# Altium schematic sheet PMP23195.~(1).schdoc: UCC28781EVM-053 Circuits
size 431 x 279 mm; Date: Not shown in title block; ApprovedBy: Not shown in title block; CheckedBy: Not shown in title block; Author: Not shown in title block; CompanyName: Not shown in title block; DrawnBy: U. Goerke; Engineer: Not shown in title block; Organization: Not shown in title block; Address1: Not shown in title block; Address2: Not shown in title block; Address3: Not shown in title block; Address4: Not shown in title block; DocumentNumber: 1; Revision: Use project parameter SCH_Rev; SheetNumber: 1; SheetTotal: 2; PageSetup: Record=PageOptions¦CenterHorizontal=True¦CenterVertical=True¦PrintScale=1.00¦XCorrection=1.00¦YCorrection=1.00¦PrintKind=0¦BorderSize=5000000¦LeftOffset=0¦BottomOffset=0¦Orientation=2¦PaperLength=1000¦PaperWidth=1000¦Scale=100¦PaperSource=15¦PrintQuality=600¦MediaType=1¦DitherType=10¦PaperKind=Letter¦PrintScaleMode=1
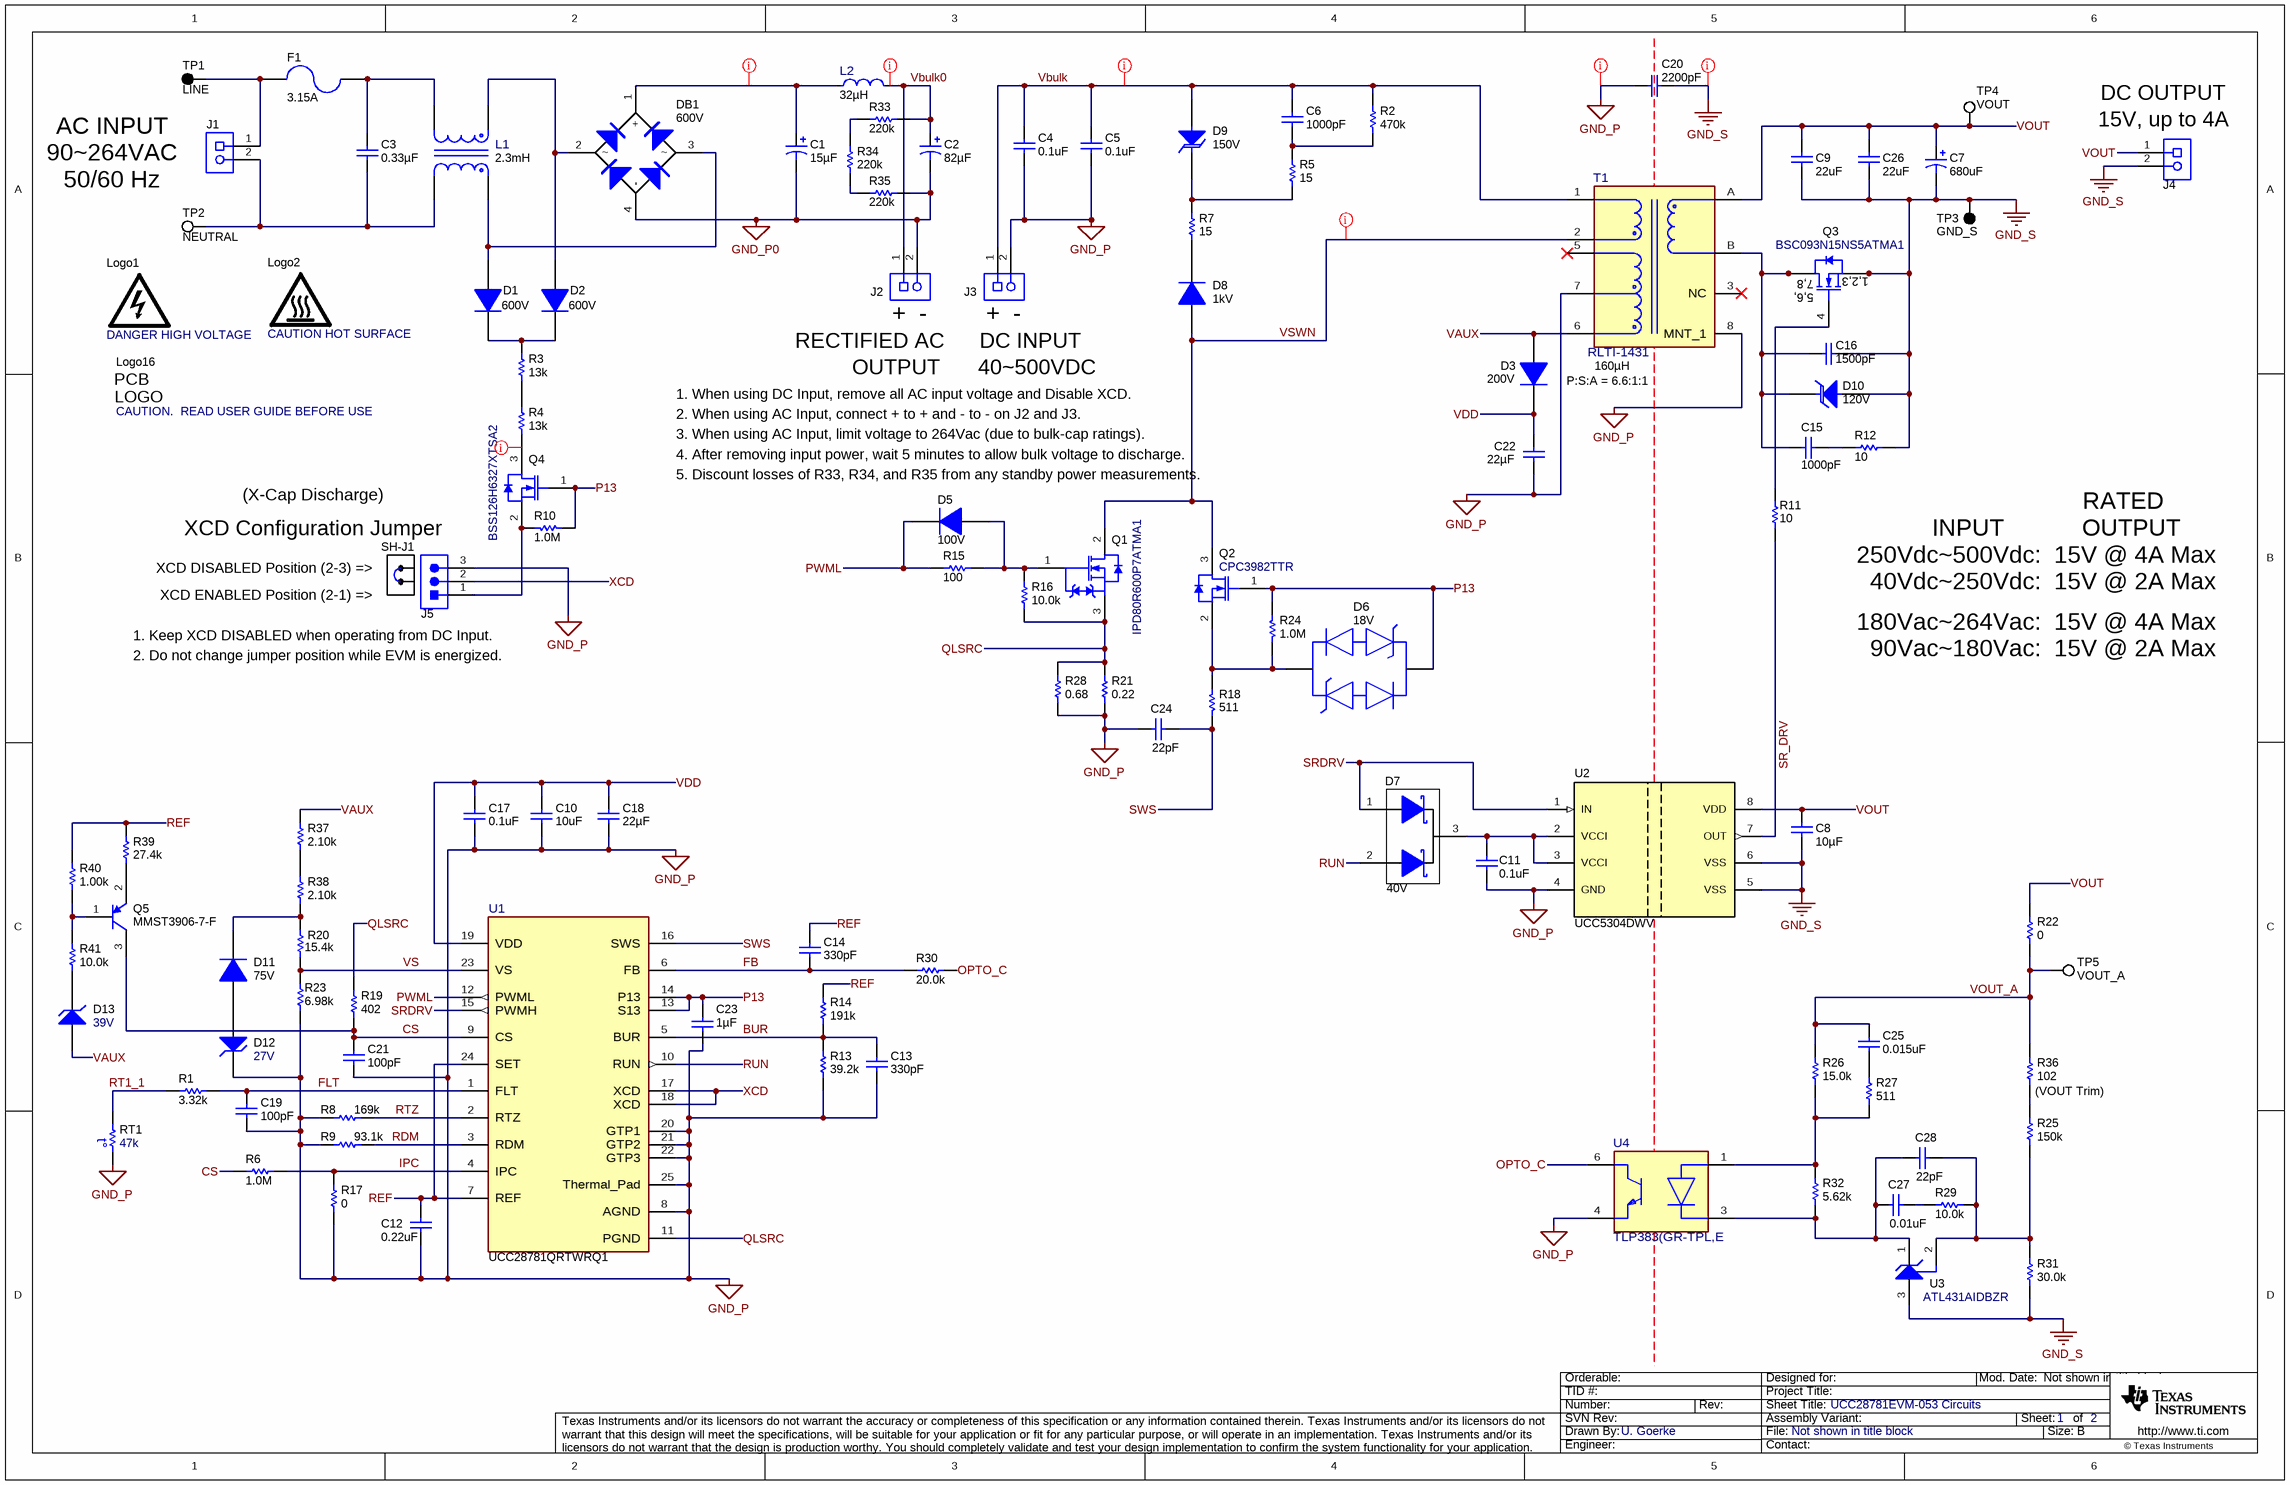
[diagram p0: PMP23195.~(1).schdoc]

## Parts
C1  ValueDisplayed: 15µF  [UVC_1000x1600]  (hidden comment: UVC2G150MPD)
C2  ValueDisplayed: 82µF  [Rubycon_1800x2500_HD]  (hidden comment: 400BXW82MEFR18X25)
C3  ValueDisplayed: 0.33µF  [WCAP-FTX2_1500x850]  (hidden comment: 890324024003)
C4  ValueDisplayed: 0.1uF  [1210_280]  (hidden comment: C1210C104KBRAC7800)
C5  ValueDisplayed: 0.1uF  [1210_280]  (hidden comment: C1210C104KBRAC7800)
C6  ValueDisplayed: 1000pF  [1206L]  (hidden comment: GRM31BR72J102KW01L)
C7  ValueDisplayed: 680uF  [PSG_1000x1150]  (hidden comment: APSG200ELL681MJB5S)
C8  ValueDisplayed: 10µF  [1206_180L]  (hidden comment: C1206C106J3RACAUTO)
C9  ValueDisplayed: 22uF  [1210_270L]  (hidden comment: GRM32ER71E226KE15L)
C10  ValueDisplayed: 10uF  [1206_180L]  (hidden comment: C3216X5R1H106K160AB)
C11  ValueDisplayed: 0.1uF  [0402S]  (hidden comment: GRM155R71H104ME14D)
C12  ValueDisplayed: 0.22uF  [0402S]  (hidden comment: GRM155R71C224KA12D)
C13  ValueDisplayed: 330pF  [0402S]  (hidden comment: GRM155R71H331KA01D)
C14  ValueDisplayed: 330pF  [0402S]  (hidden comment: GRM155R71H331KA01D)
C15  ValueDisplayed: 1000pF  [0805L]  (hidden comment: GRM21AR72E102KW01D)
C16  ValueDisplayed: 1500pF  [0805_HV1]  (hidden comment: GRM21AR72E152KW01D)
C17  ValueDisplayed: 0.1uF  [0402S]  (hidden comment: GRM155R71H104ME14D)
C18  ValueDisplayed: 22µF  [1210L]  (hidden comment: GMK325BJ226MM-P)
C19  ValueDisplayed: 100pF  [0402S]  (hidden comment: GRM1555C1H101JA01D)
C20  ValueDisplayed: 2200pF  [C900_9x13]  (hidden comment: C921U222MVVDBA7317)
C21  ValueDisplayed: 100pF  [0402S]  (hidden comment: GRM1555C1H101JA01D)
C22  ValueDisplayed: 22µF  [1210L]  (hidden comment: GMK325BJ226MM-P)
C23  Cap_F: 1µF  [0603S]  (hidden comment: CGA3E1X7R1V105K080AC)
C24  ValueDisplayed: 22pF  [0402S]  (hidden comment: GCM1555C1H220JA16D)
C25  ValueDisplayed: 0.015uF  [0402S]  (hidden comment: GRM155R71H153KA12D)
C26  ValueDisplayed: 22uF  [1210_270L]  (hidden comment: GRM32ER71E226KE15L)
C27  ValueDisplayed: 0.01uF  [0402S]  (hidden comment: GRM155R71H103KA88D)
C28  ValueDisplayed: 22pF  [0402S]  (hidden comment: GCM1555C1H220JA16D)
D1  Vr_V: 600V  [TUMD2SM]  (hidden comment: RFU02VSM6STR)
D2  Vr_V: 600V  [TUMD2SM]  (hidden comment: RFU02VSM6STR)
D3  Vr_V: 200V  [SOD-123H]  (hidden comment: CSFMT104-HF)
D5  Vr_V: 100V  [SOD-323]  (hidden comment: BAS316,115)
D6  value 18V  [FP-CDSOD323-T18C_SOD323-MFG]  (hidden comment: CDSOD323-T18C)
D7  Vr_V: 40V  [SOT-323]  (hidden comment: BAS40W-05-7-F)
D8  Vr_V: 1kV  [SMA]  (hidden comment: MRA4007T3G)
D9  VRWM: 150V  [SMA]  (hidden comment: SMAJ150A)
D10  VRWM: 120V  [SMA]  (hidden comment: SMAJ120A)
D11  Vr_V: 75V  [SOD-523]  (hidden comment: 1N4148X-TP)
D12  value 27V  [SOD-323]  (hidden comment: SZMM3Z27VST1G)
D13  value 39V  [SOD-523]  (hidden comment: BZT585B39T-7)
DB1  value 600V  [Z4-D]  (hidden comment: Z4DGP406L-HF)
F1  Irating_A: 3.15A  [FUSE_392]  (hidden comment: 39213150000)
J1  ED120/2DS  [On-Shore_ED120_2DS]  (value not drawn)
J2  ED120/2DS  [On-Shore_ED120_2DS]  (value not drawn)
J3  ED120/2DS  [On-Shore_ED120_2DS]  (value not drawn)
J4  ED120/2DS  [On-Shore_ED120_2DS]  (value not drawn)
J5  TSW-103-07-G-S  [TSW-103-07-G-S]  (value not drawn)
L1  Ind_H: 2.3mH  [FP-RLTI-1387_PTH_CMC_0IN38_0IN60-MFG]  (hidden comment: RLTI-1387)
L2  Ind_H: 32µH  [FP-7447052_PTH_D10MM0-MFG]  (hidden comment: 7447052)
Logo1  DANGER HIGH VOLTAGE  [IEC_HighVoltage_Small]  (no BOM)
Logo2  CAUTION HOT SURFACE  [IEC_HotSurface_Small]  (no BOM)
Logo16  CAUTION.  READ USER GUIDE BEFORE USE  [IEC_Caution_Small]  (no BOM)
Q1  IPD80R600P7ATMA1  [DPAK]
Q2  CPC3982TTR  [SOT-23L]
Q3  BSC093N15NS5ATMA1  [PG-TDSON-8]
Q4  BSS126H6327XTSA2  [SOT-23L]
Q5  MMST3906-7-F  [SOT-323]
R1  ValueDisplayed: 3.32k  [0402S]  (hidden comment: CRCW04023K32FKED)
R2  ValueDisplayed: 470k  [0805_HV1]  (hidden comment: CRCW0805470KJNEA)
R3  ValueDisplayed: 13k  [1206L]  (hidden comment: CRCW120613K0JNEA)
R4  ValueDisplayed: 13k  [1206L]  (hidden comment: CRCW120613K0JNEA)
R5  ValueDisplayed: 15  [0805_HV1]  (hidden comment: CRCW080515R0JNEA)
R6  ValueDisplayed: 1.0M  [0402S]  (hidden comment: CRCW04021M00JNED)
R7  ValueDisplayed: 15  [0805_HV1]  (hidden comment: CRCW080515R0JNEA)
R8  ValueDisplayed: 169k  [0402S]  (hidden comment: CRCW0402169KFKED)
R9  ValueDisplayed: 93.1k  [0402S]  (hidden comment: CRCW040293K1FKED)
R10  ValueDisplayed: 1.0M  [0402S]  (hidden comment: CRCW04021M00JNED)
R11  ValueDisplayed: 10  [0402S]  (hidden comment: CRCW040210R0JNED)
R12  ValueDisplayed: 10  [1206L]  (hidden comment: CRCW120610R0JNEA)
R13  ValueDisplayed: 39.2k  [0402S]  (hidden comment: CRCW040239K2FKED)
R14  ValueDisplayed: 191k  [0402S]  (hidden comment: CRCW0402191KFKED)
R15  ValueDisplayed: 100  [0805_HV1]  (hidden comment: CRCW0805100RJNEA)
R16  ValueDisplayed: 10.0k  [0402S]  (hidden comment: CRCW040210K0FKED)
R17  ValueDisplayed: 0  [0402S]  (hidden comment: CRCW04020000Z0EDHP)
R18  ValueDisplayed: 511  [0402S]  (hidden comment: CRCW0402511RFKED)
R19  ValueDisplayed: 402  [0402S]  (hidden comment: CRCW0402402RFKED)
R20  ValueDisplayed: 15.4k  [0402S]  (hidden comment: CRCW040215K4FKED)
R21  ValueDisplayed: 0.22  [1210L]  (hidden comment: MCR25JZHFLR220)
R22  ValueDisplayed: 0  [0402S]  (hidden comment: RC0402JR-070RL)
R23  ValueDisplayed: 6.98k  [0402S]  (hidden comment: CRCW04026K98FKED)
R24  ValueDisplayed: 1.0M  [0402S]  (hidden comment: CRCW04021M00JNED)
R25  ValueDisplayed: 150k  [0402S]  (hidden comment: ERJ-2RKF1503X)
R26  ValueDisplayed: 15.0k  [0402S]  (hidden comment: CRCW040215K0FKED)
R27  ValueDisplayed: 511  [0402S]  (hidden comment: CRCW0402511RFKED)
R28  ValueDisplayed: 0.68  [0805_HV1]  (hidden comment: ERJ-6RQFR68V)
R29  ValueDisplayed: 10.0k  [0402S]  (hidden comment: CRCW040210K0FKED)
R30  ValueDisplayed: 20.0k  [0402S]  (hidden comment: CRCW040220K0FKED)
R31  ValueDisplayed: 30.0k  [0402S]  (hidden comment: CRCW040230K0FKED)
R32  ValueDisplayed: 5.62k  [0402S]  (hidden comment: CRCW04025K62FKED)
R33  ValueDisplayed: 220k  [1206]  (hidden comment: CRCW1206220KJNEA)
R34  ValueDisplayed: 220k  [1206]  (hidden comment: CRCW1206220KJNEA)
R35  ValueDisplayed: 220k  [1206]  (hidden comment: CRCW1206220KJNEA)
R36  ValueDisplayed: 102  [0402S]  (hidden comment: CRCW0402102RFKED)
R37  ValueDisplayed: 2.10k  [0402S]  (hidden comment: CRCW04022K10FKED)
R38  ValueDisplayed: 2.10k  [0402S]  (hidden comment: CRCW04022K10FKED)
R39  ValueDisplayed: 27.4k  [0402S]  (hidden comment: CRCW040227K4FKED)
R40  ValueDisplayed: 1.00k  [0402S]  (hidden comment: CRCW04021K00FKED)
R41  ValueDisplayed: 10.0k  [0402S]  (hidden comment: CRCW040210K0FKED)
RT1  value 47k  [0603S]  (hidden comment: NCP18WB473J03RB)
SH-J1  SNT-100-BK-T-H  [SNT-100-BK-x-H]  (value not drawn)
T1  RLTI-1431  Ind_H: 160µH  [FP-RLTI-1431_PTH8_1IN0_0IN91-MFG]
TP1  LINE  [Keystone5011]
TP2  NEUTRAL  [Keystone5012]
TP3  GND_S  [Keystone5011]
TP4  VOUT  [Keystone5012]
TP5  VOUT_A  [Keystone5012]
U1  UCC28781QRTWRQ1  [RTW0024B-MFG]
U2  UCC5304DWV  [DWV0008A]
U3  ATL431AIDBZR  [DBZ0003A_L]
U4  TLP383(GR-TPL,E  [FP-TLP383(GR-TPL,E_SO6-4-MFG]

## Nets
GND_P: C4.1 C5.1 C10.2 C11.2 C12.2 C13.2 C17.2 C18.1 C19.1 C20.2 C21.2 C22.1 C23.2 C24.1 D12.1(K) J3.2 J5.3 R8.1 R9.1 R13.2 R17.1 R21.1 R23.1 R28.2 RT1.2 T1.7 T1.8(MNT_1) U1.8(AGND) U1.20(GTP1) U1.21(GTP2) U1.22(GTP3) U1.25(Thermal_Pad) U2.4(GND) U4.4(Emitter)
GND_P0: C1.2(-) C2.2(-) DB1.4(-) J2.2 R35.1
GND_S: C7.2(-) C8.2 C9.2 C16.2 C20.1 C26.2 D10.2(A) J4.2 Q3.1(S) Q3.2(S) Q3.3(S) R12.1 R31.2 TP3.1 U2.5(VSS) U2.6(VSS) U3.3(ANODE)
BUR: C13.1 R13.1 R14.2 U1.5(BUR)
CS: C21.1 Q5.3(C) R6.2 R19.1 U1.9(CS)
FB: C14.2 R30.1 U1.6(FB)
FLT: C19.2 R1.2 U1.1(FLT)
IPC: R6.1 R17.2 U1.4(IPC)
OPTO_C: R30.2 U4.6(Collector)
P13: C23.1 D6.2 Q2.1(G) Q4.1(G) R10.2 R24.2 U1.13(S13) U1.14(P13)
PWML: D5.1(K) R15.1 U1.12(PWML)
QLSRC: Q1.3(S) R16.1 R19.2 R21.2 R28.1 U1.11(PGND)
RDM: R9.2 U1.3(RDM)
REF: C12.1 C14.1 R14.1 R39.1 R40.1 U1.7(REF) U1.24(SET)
RT1_1: R1.1 RT1.1
RTZ: R8.2 U1.2(RTZ)
RUN: D7.2(A) U1.10(RUN)
SR_DRV: R11.1 U2.7(OUT)
SRDRV: D7.1(A) U1.15(PWMH) U2.1(IN)
SWS: C24.2 R18.1 U1.16(SWS)
VAUX: D3.2(A) D13.2(A) R37.1 T1.6
Vbulk: C4.2 C5.2 C6.1 D9.2(A) J3.1 R2.2 T1.1
Vbulk0: C2.1(+) J2.1 L2.2 R33.2
VDD: C10.1 C17.1 C18.2 C22.2 D3.1(K) U1.19(VDD)
VOUT: C7.1(+) C8.1 C9.1 C26.1 J4.1 R22.1 T1.A TP4.1 U2.8(VDD)
VOUT_A: C25.2 R22.2 R26.2 R36.1 TP5.1
VS: R20.2 R23.2 U1.23(VS)
VSWN: D8.2(A) Q1.2(D) Q2.3(D) T1.2
XCD: J5.2 U1.17(XCD) U1.18(XCD)
NetC1_1: C1.1(+) DB1.1(+) L2.1
NetC3_1: C3.1 J1.2 L1.2 TP2.1
NetC3_2: C3.2 F1.1 L1.3
NetC6_2: C6.2 R2.1 R5.2
NetC11_1: C11.1 D7.3(K) U2.2(VCCI) U2.3(VCCI)
NetC15_1: C15.1 R12.2
NetC15_2: C15.2 C16.1 D10.1(K) Q3.5(D) Q3.6(D) Q3.7(D) Q3.8(D) Q3.9(D) T1.B
NetC25_1: C25.1 R27.2
NetC27_1: C27.1 R29.1
NetC27_2: C27.2 C28.1 R32.1 U3.1(CATHODE) U4.3(Cathode)
NetC28_2: C28.2 R25.1 R29.2 R31.1 U3.2(REF)
NetD1_1: D1.1(K) D2.1(K) R3.1
NetD1_2: D1.2(A) DB1.3 L1.1
NetD2_2: D2.2(A) DB1.2 L1.4
NetD5_2: D5.2(A) Q1.1(G) R15.2 R16.2
NetD6_1: D6.1 Q2.2(S) R18.2 R24.1
NetD8_1: D8.1(K) R7.1
NetD9_1: D9.1(K) R5.1 R7.2
NetD11_1: D11.1(K) R20.1 R38.2
NetD11_2: D11.2(A) D12.2(A)
NetD13_1: D13.1(K) R41.2
NetF1_2: F1.2 J1.1 TP1.1
NetJ5_1: J5.1 Q4.2(S) R10.1
NetQ3_4: Q3.4(G) R11.2
NetQ4_3: Q4.3(D) R4.2
NetQ5_1: Q5.1(B) R40.2 R41.1
NetQ5_2: Q5.2(E) R39.2
NetR3_2: R3.2 R4.1
NetR25_2: R25.2 R36.2
NetR26_1: R26.1 R27.1 R32.2 U4.1(Anode)
NetR33_1: R33.1 R34.2
NetR34_1: R34.1 R35.2
NetR37_2: R37.2 R38.1

Not connected (* = marked no-connect by the designer): T1 3(NC)* 5*

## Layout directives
net class HV: NetC1_1, NetQ4_3, Vbulk, Vbulk0, VSWN
net class Primary: GND_P
net class Secondary: GND_S

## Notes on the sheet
- (near J4) DC OUTPUT
- 90|64VAC
- AC INPUT
- (near J4) 15V, up to 4A
- 50/60 Hz
- RECTIFIED AC
- OUTPUT
- (near J2) +  -
- (near J3) +  -
- DC INPUT
- 40~500VDC
- 1. When using DC Input, remove all AC input voltage and Disable XCD.
- 2. When using AC Input, connect + to + and - to - on J2 and J3.
- 3. When using AC Input, limit voltage to 264Vac (due to bulk-cap ratings).
- P:S:A = 6.6:1:1
- (X-Cap Discharge)
- 4. After removing input power, wait 5 minutes to allow bulk voltage to discharge.
- (near D5) 5. Discount losses of R33, R34, and R35 from any standby power measurements.
- RATED
- XCD Configuration Jumper
- (near SH-J1) XCD DISABLED Position (2-3) =>
- 250Vdc~500Vdc:  15V @ 4A Max
- INPUT            OUTPUT
- 1. Keep XCD DISABLED when operating from DC Input.
- (near SH-J1) XCD ENABLED Position (2-1) =>
- 180Vac|64Vac:  15V @ 4A Max
- 40Vdc|50Vdc:  15V @ 2A Max
- 2. Do not change jumper position while EVM is energized.
- 90Vac
  80Vac:  15V @ 2A Max
- (near R36) (VOUT Trim)

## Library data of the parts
C1 = CMP-0860955-2: CAP, AL, 15 µF, 400 V, +/- 20%, AEC-Q200 Grade 2, TH; Manufacturer: Nichicon; SizeArea_mm2: 100; CompType: Capacitor; Value2: 400V; SizeZ_mm: 18; IRMS_A: 180mA; Polarized: Y; SizeX_mm: 10; Value: 15uF; TaMin_C: -40°C; AEC Grade: 2; U/M: EA; SizeAreaWB_mm2: 144; Cap_Case: 10x16; TaMax_C: 105°C; AEC Category: Q200
C2 = CMP-0084285-1: CAP, AL, 82 µF, 400 V, +/- 20%, TH; Manufacturer: Rubycon; Polarized: Y; SizeZ_mm: 27; SizeAreaWB_mm2: 400; TaMax_C: 105°C; AEC Qualified: N; U/M: EA; SizeY_mm: 18; AEC Category: Q200; CompType: Capacitor; Cap_Case: 18x25mm; Value2: 400V; Value: 82uF; SizeArea_mm2: 324; TaMin_C: -40°C
C3 = CMP-0084596-1: CAP, Film, 0.33 µF, X2 275 VAC, +/- 10%, TH; Manufacturer: Wurth Elektronik; Cap_Case: 15x8.5mm; SizeAreaWB_mm2: 178.5; AEC Qualified: N; SizeX_mm: 15; Cap_F: 330nF; SizeY_mm: 8.5; VAC_X: 275; TaMin_C: -40°C; SizeZ_mm: 14.5; SizeArea_mm2: 127.5; Value: 0.33uF; TaMax_C: 105°C; AEC Category: Q200
C4 C5 = CMP-0009076-1: CAP, CERM, 0.1 uF, 630 V, +/- 10%, X7R, 1210; Manufacturer: Kemet; Polarized: N; Value: 0.1uF; U/M: EA; Cap_F: 100nF; Value1: Unknown; VDC_V: 630V; TaMin_C: -55°C; TaMax_C: 125°C; Cap_Case: 1210; SizeArea_mm2: 8; SizeAreaWB_mm2: 14.7; SizeX_mm: 3.2; SizeY_mm: 2.5; SizeZ_mm: 2.8; AEC Category: Q200
C6 = CMP-0008909-2: CAP, CERM, 1000 pF, 630 V, +/- 10%, X7R, 1206; Manufacturer: MuRata; TaMin_C: -55°C; Polarized: N; SizeAreaWB_mm2: 10.92; Value1: Unknown; U/M: EA; Value: 1000pF; TaMax_C: 125°C; SizeZ_mm: 1.35; SizeX_mm: 3.2; SizeY_mm: 1.6; Cap_Case: 1206; Value2: 630V; SizeArea_mm2: 5.12; Cap_F: 1nF; AEC Category: Q200
C7 = CMP-0012176-3: CAP, Aluminum Polymer, 680 uF, 20 V, +/- 20%, 0.012 ohm, TH; Manufacturer: Chemi-Con; TaMin_C: -55°C; ESR_ohm: 0.012; Polarized: Y; SizeAreaWB_mm2: 144; Value: 680uF; TaMax_C: 105°C; SizeZ_mm: 13; SizeX_mm: 10; Cap_Case: 10x11.5; Value2: 20V; SizeArea_mm2: 100; CompType: Capacitor; AEC Qualified: N; Cap_F: 680µF; IRMS_A: 5.4A; AEC Category: Q200
C8 = CMP-0081062-1: CAP, CERM, 10 µF, 25 V,+/- 5%, X7R, AEC-Q200 Grade 1, 1206; Manufacturer: Kemet; TaMin_C: -55°C; Polarized: N; SizeAreaWB_mm2: 10.92; U/M: EA; Value: 10uF; TaMax_C: 125°C; SizeZ_mm: 1.8; SizeX_mm: 3.2; SizeY_mm: 1.6; Cap_Case: 1206_180; Value2: 25V; SizeArea_mm2: 5.12; AEC Qualified: Y; AEC Grade: 1; AEC Category: Q200
C9 C26 = CMP-0009224-2: CAP, CERM, 22 uF, 25 V, +/- 10%, X7R, 1210; Manufacturer: MuRata; TaMin_C: -55°C; Polarized: N; SizeAreaWB_mm2: 14.7; Value1: Unknown; U/M: EA; Value: 22uF; TaMax_C: 125°C; SizeZ_mm: 2.7; SizeX_mm: 3.2; SizeY_mm: 2.5; Cap_Case: 1210; Value2: 25V; SizeArea_mm2: 8; Cap_F: 22µF; AEC Category: Q200
C10 = CMP-0008658-2: CAP, CERM, 10 uF, 50 V, +/- 10%, X5R, 1206; Manufacturer: TDK; TaMin_C: -55°C; ESR_ohm: 2.229m; Polarized: N; SizeAreaWB_mm2: 10.92; Value1: 0.002229 ohm; U/M: EA; Value: 10uF; TaMax_C: 85°C; SizeZ_mm: 1.8; SizeX_mm: 3.2; SizeY_mm: 1.6; Cap_Case: 1206_180; Value2: 50V; SizeArea_mm2: 5.12; Cap_F: 10µF; IRMS_A: 4.85932A; AEC Category: Q200
C11 C17 = CMP-0006675-2: CAP, CERM, 0.1 uF, 50 V, +/- 20%, X7R, 0402; Manufacturer: MuRata; TaMin_C: -55°C; Polarized: N; SizeAreaWB_mm2: 3; Value1: Unknown; U/M: EA; Value: 0.1uF; TaMax_C: 125°C; SizeZ_mm: 0.6; SizeX_mm: 1; SizeY_mm: 0.5; Cap_Case: 0402; Value2: 50V; Cap_F: 100nF; AEC Category: Q200
C12 = CMP-0006648-2: CAP, CERM, 0.22 uF, 16 V, +/- 10%, X7R, 0402; Manufacturer: MuRata; TaMin_C: -55°C; Polarized: N; SizeAreaWB_mm2: 3; Value1: Unknown; U/M: EA; Value: 0.22uF; TaMax_C: 125°C; SizeZ_mm: 0.6; SizeX_mm: 1; SizeY_mm: 0.5; Cap_Case: 0402; Value2: 16V; Cap_F: 220nF; AEC Category: Q200
C13 C14 = CMP-0006687-2: CAP, CERM, 330 pF, 50 V, +/- 10%, X7R, 0402; Manufacturer: MuRata; TaMin_C: -55°C; Polarized: N; SizeAreaWB_mm2: 3; Value1: Unknown; U/M: EA; Value: 330pF; TaMax_C: 125°C; SizeZ_mm: 0.6; SizeX_mm: 1; SizeY_mm: 0.5; Cap_Case: 0402; Value2: 50V; AEC Category: Q200
C15 = CMP-0008251-2: CAP, CERM, 1000 pF, 250 V, +/- 10%, X7R, 0805; Manufacturer: MuRata; TaMin_C: -55°C; Polarized: N; SizeAreaWB_mm2: 6.75; Value1: Unknown; U/M: EA; Value: 1000pF; TaMax_C: 125°C; SizeZ_mm: 1.45; SizeX_mm: 2; SizeY_mm: 1.25; Cap_Case: 0805; Value2: 250V; SizeArea_mm2: 2.5; Cap_F: 1nF; AEC Category: Q200
C16 = CMP-0008252-2: CAP, CERM, 1500 pF, 250 V, +/- 10%, X7R, 0805; Manufacturer: MuRata; TaMin_C: -55°C; Polarized: N; SizeAreaWB_mm2: 6.75; Value1: Unknown; U/M: EA; Value: 1500pF; TaMax_C: 125°C; SizeZ_mm: 1.45; SizeX_mm: 2; SizeY_mm: 1.25; Cap_Case: 0805; Value2: 250V; SizeArea_mm2: 2.5; Cap_F: 1.5nF; AEC Category: Q200
C18 C22 = CMP-0085817-1: CAP, CERM, 22 µF, 35 V,+/- 20%, X5R, 1210; Manufacturer: Taiyo Yuden; Value: 22uF; VDC_V: 35V; SizeZ_mm: 1.35; Cap_Case: 1210; TaMax_C: 85°C; U/M: EA; SizeAreaWB_mm2: 14.7; SizeX_mm: 3.2; SizeArea_mm2: 8; TaMin_C: -55°C; AEC Qualified: N; SizeY_mm: 2.5; AEC Category: Q200
C19 C21 = CMP-0006410-2: CAP, CERM, 100 pF, 50 V, +/- 5%, C0G/NP0, 0402; Manufacturer: MuRata; TaMin_C: -55°C; Polarized: N; SizeAreaWB_mm2: 3; Value1: Unknown; U/M: EA; Value: 100pF; TaMax_C: 125°C; SizeZ_mm: 0.6; SizeX_mm: 1; SizeY_mm: 0.5; Cap_Case: 0402; Value2: 50V; AEC Category: Q200
C20 = CMP-0078358-1: CAP, CERM, 2200 pF, X1 400 VAC/Y1 400 VAC, +/- 20%, Y5V, D9xL13mm; Manufacturer: Kemet; Cap_F: 2.2nF; SizeAreaWB_mm2: 121; VAC_X: 400V; SizeArea_mm2: 81; AEC Qualified: N; AEC Category: Q200; Value: 2200pF; TaMax_C: 125°C; SizeZ_mm: 13; TaMin_C: -40°C; SizeY_mm: 9; U/M: EA; AC_Safety: X1Y1; Cap_Case: 9x13mm
C23 = CMP-0007067-4: CAP, CERM, 1 uF, 35 V, +/- 10%, X7R, AEC-Q200 Grade 1, 0603; Manufacturer: TDK; TaMin_C: -55°C; ESR_ohm: 5.522m; Polarized: N; SizeAreaWB_mm2: 4.68; Value1: 0.005522 ohm; U/M: EA; Value: 1uF; TaMax_C: 125°C; SizeZ_mm: 1; SizeX_mm: 1.6; SizeY_mm: 0.8; Cap_Case: 0603; Value2: 35V; SizeArea_mm2: 1.28; AEC Qualified: Y; IRMS_A: 2.21617A; AEC Category: Q200
C24 C28 = CMP-0006348-2: CAP, CERM, 22 pF, 50 V, +/- 5%, C0G/NP0, AEC-Q200 Grade 1, 0402; Manufacturer: MuRata; TaMin_C: -55°C; Polarized: N; SizeAreaWB_mm2: 3; Value1: Unknown; U/M: EA; Value: 22pF; TaMax_C: 125°C; SizeZ_mm: 0.6; SizeX_mm: 1; SizeY_mm: 0.5; Cap_Case: 0402; Value2: 50V; AEC Qualified: Y; AEC Category: Q200
C25 = CMP-0006679-2: CAP, CERM, 0.015 uF, 50 V, +/- 10%, X7R, 0402; Manufacturer: MuRata; TaMin_C: -55°C; Polarized: N; SizeAreaWB_mm2: 3; Value1: Unknown; U/M: EA; TaMax_C: 125°C; SizeZ_mm: 0.6; SizeX_mm: 1; SizeY_mm: 0.5; Cap_Case: 0402; Value2: 50V; Cap_F: 15nF; AEC Category: Q200
C27 = CMP-0006674-2: CAP, CERM, 0.01 uF, 50 V, +/- 10%, X7R, 0402; Manufacturer: MuRata; TaMin_C: -55°C; Polarized: N; SizeAreaWB_mm2: 3; Value1: Unknown; U/M: EA; Value: 0.01uF; TaMax_C: 125°C; SizeZ_mm: 0.6; SizeX_mm: 1; SizeY_mm: 0.5; Cap_Case: 0402; Value2: 50V; Cap_F: 10nF; AEC Category: Q200
D1 D2 = CMP-0080762-2: Diode, Standard Recovery Rectifier, 600 V, 0.2 A, 2x1.4mm; Manufacturer: Rohm; SizeArea_mm2: 3.5; AEC Qualified: N; SizeY_mm: 1.4; Io_A: 200mA; SizeZ_mm: 0.8; Vf_V: 2.2V; SizeAreaWB_mm2: 8.4; TJmax_C: 150°C; Value1: 0.2A; SizeX_mm: 2.5; AEC Category: Q101; Value: 600V
D3 = CMP-0029199-2: Diode, Superfast Rectifier, 200 V, 1 A, 3.5x1.6mm; Manufacturer: Comchip Technology; Vf_V: 950mV; Value: 200V; Value1: 1A; Value2: 0.95V; TJmax_C: 150°C; SizeAreaWB_mm2: 11.7; SizeArea_mm2: 5.6; SizeX_mm: 3.5; SizeY_mm: 1.6; SizeZ_mm: 1; AEC Category: Q101; AEC Qualified: N
D5 = CMP-0029006-2: Diode, Ultrafast, 100 V, 0.25 A, SOD-323; Manufacturer: Nexperia; SizeY_mm: 1.35; Value1: 0.25A; SizeAreaWB_mm2: 8.695; SizeZ_mm: 1; Io_A: 250mA; Value2: 1.4V; SizeX_mm: 2.7; Green_REACh: Incomplete; TJmax_C: 150°C; Green_Lifecycle: Not Set; AEC Category: Q101; Value: 100V; SizeArea_mm2: 3.645
D6 = CMP-0087587-1: Diode, TVS, Bi, 18 V, SOD-323; Manufacturer: Bourns Inc.; SizeZ_mm: 1.14mm; AEC Qualified: No
D7 = CMP-0028437-2: Diode, Schottky, 40 V, 0.2 A, SOT-323; Manufacturer: Diodes Inc.; Io_A: 200mA; Green_Lifecycle: Not Set; SizeAreaWB_mm2: 10.24; Green_REACh: Incomplete; Value1: 0.2A; Value: 40V; SizeZ_mm: 1.1; SizeX_mm: 2.2; Vf_V: 800mV; Value2: 0.8V; SizeArea_mm2: 4.84; AEC Category: Q101
D8 = CMP-0077082-2: Diode, Standard Recovery Rectifier, 1000 V, 1 A, AEC-Q101, SMA; Manufacturer: ON Semiconductor; SizeAreaWB_mm2: 37.3428; SizeArea_mm2: 16.3228; AEC Qualified: Y; TJmax_C: 175°C; AEC Category: Q101; Value: 1000V; SizeZ_mm: 2.87; Green_REACh: Passed; Io_A: 1A; Vf_V: 1.1V; SizeY_mm: 2.92; Green_Lifecycle: Active; SizeX_mm: 5.59; RJC_CperW: 16.2
D9 = CMP-0084982-1: Diode, TVS, Uni, 150 V, 243 Vc, 400 W, 1.6 A, SMA; Manufacturer: Littelfuse; Vc: 243V; Ipp: 1.6A; RJA_CperW: 120; AEC Qualified: N; Value: 150V; Ppk: 400W; AEC Category: Q101; SizeArea_mm2: 16.3228; SizeAreaWB_mm2: 37.3428; SizeZ_mm: 2.87; Vbr_Max: 185V; SizeX_mm: 5.59; SizeY_mm: 2.92; Vbr_Min: 167V
D10 = CMP-0084980-1: Diode, TVS, Uni, 120 V, 193 Vc, 400 W, 2.1 A, SMA; Manufacturer: Littelfuse; Value: 120V; SizeX_mm: 5.59; Vc: 193V; Ipp: 2.1A; Vbr_Max: 147V; AEC Qualified: N; Vbr_Min: 133V; SizeY_mm: 2.92; Ppk: 400W; SizeZ_mm: 2.87; AEC Category: Q101; SizeAreaWB_mm2: 37.3428; RJA_CperW: 120; SizeArea_mm2: 16.3228
D11 = CMP-0076957-3: Diode, Switching, 75 V, 0.3 A, SOD-523; Manufacturer: Micro Commercial Components; SizeY_mm: 0.9; Value2: 1.25V; Value1: 0.3A; Value: 75V; Green_Lifecycle: Not Set; SizeAreaWB_mm2: 5.13; SizeArea_mm2: 1.53; SizeZ_mm: 0.65; Io_A: 300mA; TJmax_C: 150°C; SizeX_mm: 1.7; Green_REACh: Incomplete; AEC Category: Q101
D12 = CMP-0085774-1: Diode, Zener, 27 V, 300 mW, AEC-Q101, SOD-323; Manufacturer: ON Semiconductor; AEC Qualified: Y; Value1: 0.3W; SizeX_mm: 2.7; SizeZ_mm: 1; SizeArea_mm2: 3.645; SizeAreaWB_mm2: 8.695; RJA_CperW: 416; SizeY_mm: 1.35; Power_W: 300mW; AEC Category: Q101
D13 = CMP-0005889-5: Diode, Zener, 39 V, 350 mW, AEC-Q101, SOD-523; Manufacturer: Diodes Inc.; SizeZ_mm: 0.65; Value1: 0.35W; SizeAreaWB_mm2: 5.13; SizeY_mm: 0.9; AEC Qualified: Y; SizeX_mm: 1.7; SizeArea_mm2: 1.53; Power_W: 350mW; AEC Category: Q101; RJA_CperW: 357
DB1 = Z4DGP406L-HF: Diode, P-N-Bridge, 600 V, 4 A, Z4-D; Manufacturer: Comchip Technology; U/M: EA; Vf_V: 0.95; Value1: 4A; Value2: 0.95V; Io_A: 4; Vr_V: 600; TJmax_C: 175; SizeAreaWB_mm2: 126.25; SizeArea_mm2: 85.05; SizeX_mm: 10.5; SizeY_mm: 8.1; SizeZ_mm: 1.55; AEC Category: Q101; AEC Qualified: N; Green_Lifecycle: Not Set; Green_REACh: Incomplete
F1 = CMP-0003561-2: Fuse, 3.15 A, 250VAC/VDC, TH; Manufacturer: Littelfuse; VAC_V: 250V
J1-J4 = CMP-0074910-1: Terminal Block, 5.08 mm, 2x1, Brass, TH; Manufacturer: On-Shore Technology; Pitch_mm: 5.08; Gender: Female; Shrouded: N; Row_Count: 1; Current_A: 15A; Voltage_V: 300V; Cert_CULUS: Y; CNHeader: False; CT: True; Green_Lifecycle: Not Set; Green_REACh: Incomplete
J5 = CMP-0075407-2: Header, 100mil, 3x1, Gold, TH; Manufacturer: Samtec; Pitch_mm: 2.54; Cert_VDE: N; Gender: Male; Cert_CSA: Y; Voltage_V: 550V; Green_REACh: Passed; Current_A: 6.3A; Green_Lifecycle: Active; Row_Count: 1
L1 = CMP-0092946-1: Common Mode Choke, 2.3mH 35%, 0.6x0.38x0.75 IN; Manufacturer: Renco; Test Frequency: 10kHz; SizeZ_mm: 0.75inch; DCR_ohm: 0.03; AEC Qualified: No
L2 = CMP-0087546-1: WE-FI Leaded Toroidal Line Choke; Manufacturer: Wurth; SizeZ_mm: 10mm; Irms: 2.6A; DCR_ohm: 0.045; AEC Qualified: No; Symbol Name: SYM-7447052
Logo1 = CMP-0074835-1: IEC 61010-1 High Voltage Warning; SymbolCreator: a0412235
Logo2 = CMP-0074837-1: IEC 61010-1 Hot Surface Warning; SymbolCreator: a0412235
Logo16 = CMP-0074836-1: IEC 61010-1 Caution Warning; SymbolCreator: a0412235; Lib Reference: IEC_Caution
Q1 = CMP-0083711-2: MOSFET, N-CH, 800 V, 8 A, DPAK; Manufacturer: Infineon Technologies; Alternate Manufacturer: None; AEC Qualified: N; Vgs_V: 20V; SizeY_mm: 6.54; VdsMax_V: 800V; IdsMax_A: 8A; SizeX_mm: 9.91; Value2: 20 nC; AEC Category: Q101; ChMode: Enhancement; SizeAreaWB_mm2: 101.7114; Value1: ? ohm; SizeArea_mm2: 64.8114; Value: 800V; SizeZ_mm: 2.29; QgTyp_nC: 20
Q2 = CMP-0081263-2: MOSFET, N-CH, Depletion Mode, 800 V, SOT-23; Alternate Manufacturer: None; Manufacturer: IXYS; SizeAreaWB_mm2: 14; Vgs_V: 15V; Value1: ? ohm; VdsMax_V: 800V; Value: 800V; SizeZ_mm: 1.1; SizeX_mm: 2.5; SizeY_mm: 3; Value2: ? nC; SizeArea_mm2: 7.5; ChType: N; AEC Category: Q101
Q3 = CMP-0001046-2: MOSFET, N-CH, 150 V, 87 A, PG-TDSON-8; Alternate Manufacturer: None; Manufacturer: Infineon Technologies; SizeZ_mm: 1.12; ChType: N; Value2: 33 nC; VdsMax_V: 150V; SizeX_mm: 5.99; SizeY_mm: 4.9; Vgs_V: 20V; QgTyp_nC: 33; Value: 150V; SizeArea_mm2: 29.351; AEC Category: Q101; IdsMax_A: 87A; SizeAreaWB_mm2: 55.131; U/M: EA
Q4 = CMP-0067574-2: MOSFET, N-CH, Depletion Mode, 100 V, 0.17 A, AEC-Q101, SOT-23; Manufacturer: Infineon Technologies; Alternate Manufacturer: None; ChType: N; Value: 600V; Value1: ? ohm; Value2: 1.4 nC; QgTyp_nC: 1.4; Vgs_V: 20V; IdsMax_A: 21mA; SizeAreaWB_mm2: 14.0; SizeArea_mm2: 7.5; SizeX_mm: 2.5; SizeY_mm: 3.0; SizeZ_mm: 1.1; AEC Category: Q101; AEC Qualified: Y
Q5 = CMP-0077878-2: Transistor, PNP, 40 V, 0.2 A, AEC-Q101, SOT-323; Manufacturer: Diodes Inc.; Vcesat1_V: 300mV; AEC Qualified: Y; CompType: BJT; PNP: 1.0; Vceo_V: 40V; AEC Category: Q101; NPN: 0.0; Value1: 0.2 A; HfeMax: 300.0; TaMax_C: 150°C; SizeAreaWB_mm2: 10.24; SizeZ_mm: 1.1; SizeY_mm: 2.2; Value: 40 V; SizeArea_mm2: 4.84; IcRated_A: 200mA; TaMin_C: -55°C
R1 = CMP-0026333-2: RES, 3.32 k, 1%, 0.063 W, AEC-Q200 Grade 0, 0402; Manufacturer: Vishay-Dale; Power_W: 63mW; TempCo: 100 ppm/C; Value_Code: 3k32; Value: 3.32k; EIA_Code: E96; SizeX_mm: 1; SizeY_mm: 0.5; SizeZ_mm: 0.6; Value2: 0.063W; AEC Qualified: Y; VDC_V: 50V; AEC Category: Q200; AEC Grade: 0
R2 = CMP-0020554-3: RES, 470 k, 5%, 0.125 W, AEC-Q200 Grade 0, 0805; Manufacturer: Vishay-Dale; Power_W: 125mW; TempCo: 200 ppm/C; Value: 470k; EIA_Code: E24; SizeX_mm: 2; SizeY_mm: 1.25; SizeZ_mm: 1.45; Value2: 0.125W; SizeArea_mm2: 2.5; AEC Qualified: Y; VDC_V: 150V; AEC Category: Q200; AEC Grade: 0
R3 R4 = CMP-0018589-3: RES, 13 k, 5%, 0.25 W, AEC-Q200 Grade 0, 1206; Manufacturer: Vishay-Dale; Power_W: 250mW; TempCo: 200 ppm/C; Value_Code: 13k0; Value: 13k; EIA_Code: E24; SizeX_mm: 3.2; SizeY_mm: 1.6; SizeZ_mm: 1.35; Value2: 0.25W; SizeArea_mm2: 5.12; AEC Qualified: Y; VDC_V: 200V; AEC Category: Q200; AEC Grade: 0
R5 R7 = CMP-0020464-3: RES, 15, 5%, 0.125 W, AEC-Q200 Grade 0, 0805; Manufacturer: Vishay-Dale; Power_W: 125mW; TempCo: 200 ppm/C; Value_Code: 15R0; Value: 15; EIA_Code: E24; SizeX_mm: 2; SizeY_mm: 1.25; SizeZ_mm: 1.45; Value2: 0.125W; SizeArea_mm2: 2.5; AEC Qualified: Y; VDC_V: 150V; AEC Category: Q200; AEC Grade: 0
R6 = CMP-0026859-2: RES, 1.0 M, 5%, 0.063 W, AEC-Q200 Grade 0, 0402; Manufacturer: Vishay-Dale; Power_W: 63mW; TempCo: 200 ppm/C; Value_Code: 1M00; Value: 1.0Meg; EIA_Code: E24; Res_ohm: 1M; SizeX_mm: 1; SizeY_mm: 0.5; SizeZ_mm: 0.6; Value2: 0.063W; AEC Qualified: Y; VDC_V: 50V; AEC Category: Q200; AEC Grade: 0
R8 = CMP-0026038-3: RES, 169 k, 1%, 0.063 W, AEC-Q200 Grade 0, 0402; Manufacturer: Vishay-Dale; Power_W: 63mW; TempCo: 100 ppm/C; Value: 169k; EIA_Code: E96; SizeX_mm: 1; SizeY_mm: 0.5; SizeZ_mm: 0.6; Value2: 0.063W; AEC Qualified: Y; VDC_V: 50V; AEC Category: Q200; AEC Grade: 0
R9 = CMP-0026609-3: RES, 93.1 k, 1%, 0.063 W, AEC-Q200 Grade 0, 0402; Manufacturer: Vishay-Dale; VDC_V: 50V; Value: 93.1k; SizeArea_mm2: 0.5; SizeX_mm: 1; AEC Qualified: Y; Value_Code: 93k1; EIA_Code: E96; AEC Category: Q200; TempCo: 100 ppm/C; Value2: 0.063W; AEC Grade: 0; SizeZ_mm: 0.6; Power_W: 63mW
R10 R24 = CMP-0026859-2: RES, 1.0 M, 5%, 0.063 W, AEC-Q200 Grade 0, 0402; Manufacturer: Vishay-Dale; Value: 1.0Meg; Res_ohm: 1M; Value_Code: 1M00; Power_W: 63mW; Value2: 0.063W; VDC_V: 50V; TempCo: 200 ppm/C; SizeArea_mm2: 0.5; SizeX_mm: 1; SizeZ_mm: 0.6; EIA_Code: E24; AEC Category: Q200; AEC Qualified: Y; AEC Grade: 0
R11 = CMP-0026827-3: RES, 10, 5%, 0.063 W, AEC-Q200 Grade 0, 0402; Manufacturer: Vishay-Dale; Power_W: 63mW; TempCo: 200 ppm/C; Value_Code: 10R0; Value: 10; EIA_Code: E24; SizeX_mm: 1; SizeY_mm: 0.5; SizeZ_mm: 0.6; Value2: 0.063W; AEC Qualified: Y; VDC_V: 50V; AEC Category: Q200; AEC Grade: 0
R12 = CMP-0018578-3: RES, 10, 5%, 0.25 W, AEC-Q200 Grade 0, 1206; Manufacturer: Vishay-Dale; Power_W: 250mW; TempCo: 200 ppm/C; Value_Code: 10R0; Value: 10; EIA_Code: E24; SizeX_mm: 3.2; SizeY_mm: 1.6; SizeZ_mm: 1.35; Value2: 0.25W; SizeArea_mm2: 5.12; AEC Qualified: Y; VDC_V: 200V; AEC Category: Q200; AEC Grade: 0
R13 = CMP-0026327-2: RES, 39.2 k, 1%, 0.063 W, AEC-Q200 Grade 0, 0402; Manufacturer: Vishay-Dale; Power_W: 63mW; TempCo: 100 ppm/C; Value_Code: 39k2; Value: 39.2k; EIA_Code: E96; SizeX_mm: 1; SizeY_mm: 0.5; SizeZ_mm: 0.6; Value2: 0.063W; AEC Qualified: Y; VDC_V: 50V; AEC Category: Q200; AEC Grade: 0
R14 = CMP-0026063-3: RES, 191 k, 1%, 0.063 W, AEC-Q200 Grade 0, 0402; Manufacturer: Vishay-Dale; Power_W: 63mW; TempCo: 100 ppm/C; Value: 191k; EIA_Code: E96; SizeX_mm: 1; SizeY_mm: 0.5; SizeZ_mm: 0.6; Value2: 0.063W; AEC Qualified: Y; VDC_V: 50V; AEC Category: Q200; AEC Grade: 0
R15 = CMP-0020445-3: RES, 100, 5%, 0.125 W, AEC-Q200 Grade 0, 0805; Manufacturer: Vishay-Dale; Power_W: 125mW; TempCo: 200 ppm/C; Value_Code: 100R; Value: 100; EIA_Code: E24; SizeX_mm: 2; SizeY_mm: 1.25; SizeZ_mm: 1.45; Value2: 0.125W; SizeArea_mm2: 2.5; AEC Qualified: Y; VDC_V: 150V; AEC Category: Q200; AEC Grade: 0
R16 R29 R41 = CMP-0025958-3: RES, 10.0 k, 1%, 0.063 W, AEC-Q200 Grade 0, 0402; Manufacturer: Vishay-Dale; Power_W: 63mW; TempCo: 100 ppm/C; Value_Code: 10k0; Value: 10.0k; EIA_Code: E96; Res_ohm: 10k; SizeX_mm: 1; SizeY_mm: 0.5; SizeZ_mm: 0.6; Value2: 0.063W; AEC Qualified: Y; VDC_V: 50V; AEC Category: Q200; AEC Grade: 0
R17 = CMP-0081856-1: RES, 0, 0%, 0.2 W, AEC-Q200 Grade 0, 0402; Manufacturer: Vishay-Dale; SizeAreaWB_mm2: 3; SizeArea_mm2: 0.5; AEC Qualified: Y; AEC Category: Q200; Value: 0; SizeZ_mm: 0.6; Power_W: 200mW; VDC_V: 50V; Value2: 0.2W; SizeX_mm: 1
R18 R27 = CMP-0026436-2: RES, 511, 1%, 0.063 W, AEC-Q200 Grade 0, 0402; Manufacturer: Vishay-Dale; Power_W: 63mW; TempCo: 100 ppm/C; Value_Code: 511R; Value: 511; EIA_Code: E96; SizeX_mm: 1; SizeY_mm: 0.5; SizeZ_mm: 0.6; Value2: 0.063W; AEC Qualified: Y; VDC_V: 50V; AEC Category: Q200; AEC Grade: 0
R19 = CMP-0026366-2: RES, 402, 1%, 0.063 W, AEC-Q200 Grade 0, 0402; Manufacturer: Vishay-Dale; Power_W: 63mW; TempCo: 100 ppm/C; Value_Code: 402R; Value: 402; EIA_Code: E96; SizeX_mm: 1; SizeY_mm: 0.5; SizeZ_mm: 0.6; Value2: 0.063W; AEC Qualified: Y; VDC_V: 50V; AEC Category: Q200; AEC Grade: 0
R20 = CMP-0026028-3: RES, 15.4 k, 1%, 0.063 W, AEC-Q200 Grade 0, 0402; Manufacturer: Vishay-Dale; Power_W: 63mW; TempCo: 100 ppm/C; Value_Code: 15k4; Value: 15.4k; EIA_Code: E96; SizeX_mm: 1; SizeY_mm: 0.5; SizeZ_mm: 0.6; Value2: 0.063W; AEC Qualified: Y; VDC_V: 50V; AEC Category: Q200; AEC Grade: 0
R21 = CMP-0015175-2: RES, 0.22, 1%, 0.5 W, 1210; Manufacturer: Rohm; Power_W: 500mW; TempCo: 200 ppm/C; SizeAreaWB_mm2: 14.7; Value_Code: R220; U/M: EA; Value: 0.22; EIA_Code: E96; SizeX_mm: 3.2; SizeY_mm: 2.5; SizeZ_mm: 1.35; Value2: 0.5W; SizeArea_mm2: 8; VDC_V: 0V; AEC Category: Q200
R22 = CMP-0027004-2: RES, 0, 5%, 0.063 W, 0402; Manufacturer: Yageo America; Power_W: 63mW; TempCo: 200 ppm/C; Value_Code: 0000; U/M: EA; Value: 0; EIA_Code: E24; SizeX_mm: 1; SizeY_mm: 0.5; SizeZ_mm: 0.6; Value2: 0.063W; VDC_V: 50V; AEC Category: Q200
R23 = CMP-0026518-2: RES, 6.98 k, 1%, 0.063 W, AEC-Q200 Grade 0, 0402; Manufacturer: Vishay-Dale; Power_W: 63mW; TempCo: 100 ppm/C; Value_Code: 6k98; Value: 6.98k; EIA_Code: E96; SizeX_mm: 1; SizeY_mm: 0.5; SizeZ_mm: 0.6; Value2: 0.063W; AEC Qualified: Y; VDC_V: 50V; AEC Category: Q200; AEC Grade: 0
R25 = CMP-0026669-1: RES, 150 k, 1%, 0.1 W, AEC-Q200 Grade 0, 0402; Manufacturer: Panasonic; Power_W: 100mW; TempCo: 100 ppm/C; U/M: EA; Value: 150k; EIA_Code: E96; SizeX_mm: 1; SizeY_mm: 0.5; SizeZ_mm: 0.6; Value2: 0.1W; AEC Qualified: Y; VDC_V: 50V; AEC Grade: 0; AEC Category: Q200
R26 = CMP-0026027-3: RES, 15.0 k, 1%, 0.063 W, AEC-Q200 Grade 0, 0402; Manufacturer: Vishay-Dale; Power_W: 63mW; TempCo: 100 ppm/C; Value_Code: 15k0; Value: 15.0k; EIA_Code: E96; Res_ohm: 15k; SizeX_mm: 1; SizeY_mm: 0.5; SizeZ_mm: 0.6; Value2: 0.063W; AEC Qualified: Y; VDC_V: 50V; AEC Category: Q200; AEC Grade: 0
R28 = CMP-0021844-3: RES, 0.68, 1%, 0.125 W, AEC-Q200 Grade 0, 0805; Manufacturer: Panasonic; Power_W: 125mW; TempCo: 250 ppm/C; Value_Code: R680; Value: 0.68; EIA_Code: E96; SizeX_mm: 2; SizeY_mm: 1.25; SizeZ_mm: 1.45; Value2: 0.125W; SizeArea_mm2: 2.5; AEC Qualified: Y; AEC Category: Q200; AEC Grade: 0; SizeAreaWB_mm2: 6.75
R30 = CMP-0026162-2: RES, 20.0 k, 1%, 0.063 W, AEC-Q200 Grade 0, 0402; Manufacturer: Vishay-Dale; Power_W: 63mW; TempCo: 100 ppm/C; Value_Code: 20k0; Value: 20.0k; EIA_Code: E96; Res_ohm: 20k; SizeX_mm: 1; SizeY_mm: 0.5; SizeZ_mm: 0.6; Value2: 0.063W; AEC Qualified: Y; VDC_V: 50V; AEC Category: Q200; AEC Grade: 0
R31 = CMP-0078244-2: RES, 30.0 k, 1%, 0.063 W, AEC-Q200 Grade 0, 0402; Manufacturer: Vishay-Dale; Power_W: 63mW; Green_Lifecycle: Active; TempCo: 100 ppm/C; Value_Code: 30k0; Green_REACh: Passed; Value: 30.0k; Res_ohm: 30k; SizeX_mm: 1; SizeY_mm: 0.5; SizeZ_mm: 0.6; Value2: 0.063W; AEC Qualified: Y; VDC_V: 50V; AEC Grade: 0; AEC Category: Q200
R32 = CMP-0026467-2: RES, 5.62 k, 1%, 0.063 W, AEC-Q200 Grade 0, 0402; Manufacturer: Vishay-Dale; Power_W: 63mW; TempCo: 100 ppm/C; Value_Code: 5k62; Value: 5.62k; EIA_Code: E96; SizeX_mm: 1; SizeY_mm: 0.5; SizeZ_mm: 0.6; Value2: 0.063W; AEC Qualified: Y; VDC_V: 50V; AEC Category: Q200; AEC Grade: 0
R33-R35 = CMP-0018628-3: RES, 220 k, 5%, 0.25 W, AEC-Q200 Grade 0, 1206; Manufacturer: Vishay-Dale; Power_W: 250mW; TempCo: 200 ppm/C; Value: 220k; EIA_Code: E24; SizeX_mm: 3.2; SizeY_mm: 1.6; SizeZ_mm: 1.35; Value2: 0.25W; SizeArea_mm2: 5.12; AEC Qualified: Y; VDC_V: 200V; AEC Category: Q200; AEC Grade: 0
R36 = CMP-0025953-3: RES, 102, 1%, 0.063 W, AEC-Q200 Grade 0, 0402; Manufacturer: Vishay-Dale; Power_W: 63mW; TempCo: 100 ppm/C; Value_Code: 102R; Value: 102; EIA_Code: E96; SizeX_mm: 1; SizeY_mm: 0.5; SizeZ_mm: 0.6; Value2: 0.063W; AEC Qualified: Y; VDC_V: 50V; AEC Category: Q200; AEC Grade: 0
R37 R38 = CMP-0026229-2: RES, 2.10 k, 1%, 0.063 W, AEC-Q200 Grade 0, 0402; Manufacturer: Vishay-Dale; Power_W: 63mW; TempCo: 100 ppm/C; Value_Code: 2k10; Value: 2.10k; EIA_Code: E96; Res_ohm: 2.1k; SizeX_mm: 1; SizeY_mm: 0.5; SizeZ_mm: 0.6; Value2: 0.063W; AEC Qualified: Y; VDC_V: 50V; AEC Category: Q200; AEC Grade: 0
R39 = CMP-0026213-2: RES, 27.4 k, 1%, 0.063 W, AEC-Q200 Grade 0, 0402; Manufacturer: Vishay-Dale; Power_W: 63mW; TempCo: 100 ppm/C; Value_Code: 27k4; Value: 27.4k; EIA_Code: E96; SizeX_mm: 1; SizeY_mm: 0.5; SizeZ_mm: 0.6; Value2: 0.063W; AEC Qualified: Y; VDC_V: 50V; AEC Category: Q200; AEC Grade: 0
R40 = CMP-0026071-3: RES, 1.00 k, 1%, 0.063 W, AEC-Q200 Grade 0, 0402; Manufacturer: Vishay-Dale; Power_W: 63mW; TempCo: 100 ppm/C; Value_Code: 1k00; Value: 1.00k; EIA_Code: E96; Res_ohm: 1k; SizeX_mm: 1; SizeY_mm: 0.5; SizeZ_mm: 0.6; Value2: 0.063W; AEC Qualified: Y; VDC_V: 50V; AEC Category: Q200; AEC Grade: 0
RT1 = CMP-0002523-3: Thermistor NTC, 47k ohm, 5%, 0603; Manufacturer: MuRata; TaMax_C: 125°C; SizeX_mm: 1.6; SizeY_mm: 0.8; TaMin_C: -40°C; Power_W: 100mW; SizeZ_mm: 1; SizeArea_mm2: 1.28; SizeAreaWB_mm2: 4.68; U/M: EA
SH-J1 = CMP-0077139-2: Shunt, 100mil, Tin plated, Black; Manufacturer: Samtec; Gender: Female; Cert_UL: Y; Green_REACh: Passed; Current_A: 4.3A; Green_Lifecycle: Active
T1 = CMP-0094252-2: Transformer FLYBACK for UCC28781EVM-053; Manufacturer: Renco; SizeZ_mm: 0.66inch; Ns1toNp: 1:0.151; AEC Qualified: No; Rsec1_ohm: 7m; Voltage_Isolation_Vrms: 3kV; DCR_ohm: 0.24
TP1 TP3 = CMP-0055148-1: Test Point, Multipurpose, Black, TH; Manufacturer: Keystone; CNHeader: FALSE; Green_Lifecycle: Active; Green_REACh: Passed; ContactFinish: Silver; CT: TRUE
TP2 TP4 TP5 = CMP-0055149-1: Test Point, Multipurpose, White, TH; Manufacturer: Keystone; CNHeader: FALSE; Green_Lifecycle: Active; Green_REACh: Passed; ContactFinish: Silver; CT: TRUE
U1 = CMP-0094229-1: Zero-Voltage-Switching Flyback Controller with Dedicated Synchronous Rectifier Gate-Drive; Manufacturer: Texas Instruments; Nominal Supply Current: 235-3000uA; Standoff Height: 0mm; Output Type: Other; Min Supply Voltage: 14V; TaMax_C: +125°C; TaMin_C: -40°C; Max Supply Voltage: 34V; SizeZ_mm: 0.8mm; Switching Frequency: 1.5kHz; AEC Grade: Grade 1; Number Of Outputs: 1; AEC Qualified: Yes; TJmax_C: +140°C
U2 = CMP-0860377-2: 4-A/6-A, Single-Channel Reinforced Isolation Gate Driver with High Noise Immunity, DWV0008A (SOIC-8); Manufacturer: Texas Instruments; SizeX_mm: 11.5; SizeArea_mm2: 67.275; SizeAreaWB_mm2: 105.975; CompType: IC; SizeZ_mm: 2.8; SizeY_mm: 5.85; AEC Category: Q200; AEC Qualified: N
U3 = CMP-0066199-1: 2.5V Low Iq Adjustable Precision Shunt Regulator, DBZ0003A (SOT-23-3); Manufacturer: Texas Instruments; SizeArea_mm2: 7.5; SizeAreaWB_mm2: 14.0; SizeX_mm: 2.5; SizeY_mm: 3.0; SizeZ_mm: 1.12; CompType: IC; U/M: EA
U4 = CMP-0087394-2: Optoisolator Transistor Output 5000Vrms 1 Channel 6-SO; Manufacturer: Toshiba; CTR (Max): 300%; CTR (Min): 100%; SizeZ_mm: 2.3mm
